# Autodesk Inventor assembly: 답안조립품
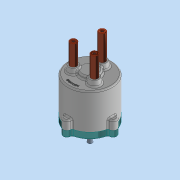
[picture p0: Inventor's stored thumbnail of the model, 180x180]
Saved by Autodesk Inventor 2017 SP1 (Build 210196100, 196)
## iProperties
Part Number: 답안조립품
Material: 일반
Document SubType Name: Assembly
Designer: MRC
Author: MRC
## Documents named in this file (14)
- C:\Users\MRC\Desktop\610708V1009\답안조립품.iam
- C:\Users\MRC\Desktop\610708V1009\본체.ipt
- C:\Users\MRC\Desktop\610708V1009\가변스프링1.ipt
- C:\Users\MRC\Desktop\610708V1009\가변스프링2.ipt
- C:\Users\MRC\Desktop\610708V1009\가변스프링3.ipt
- C:\Users\MRC\Desktop\610708V1009\멈춤링 10 x 1.ipt
- C:\Users\MRC\Desktop\610708V1009\멈춤링 22 x 1.2.ipt
- C:\Users\MRC\Desktop\610708V1009\메인 축.ipt
- C:\Users\MRC\Desktop\610708V1009\베어링 NA 4900.ipt
- C:\Users\MRC\Desktop\610708V1009\볼트 M5.ipt
- C:\Users\MRC\Desktop\610708V1009\슬라이드 축.ipt
- C:\Users\MRC\Desktop\610708V1009\오일실.ipt
- C:\Users\MRC\Desktop\610708V1009\커버.ipt
- C:\Users\MRC\Desktop\610708V1009\판캠.ipt
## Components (3 placed, 3 different names)
1. 가변스프링1:1
2. 가변스프링2:1
3. 가변스프링3:1
